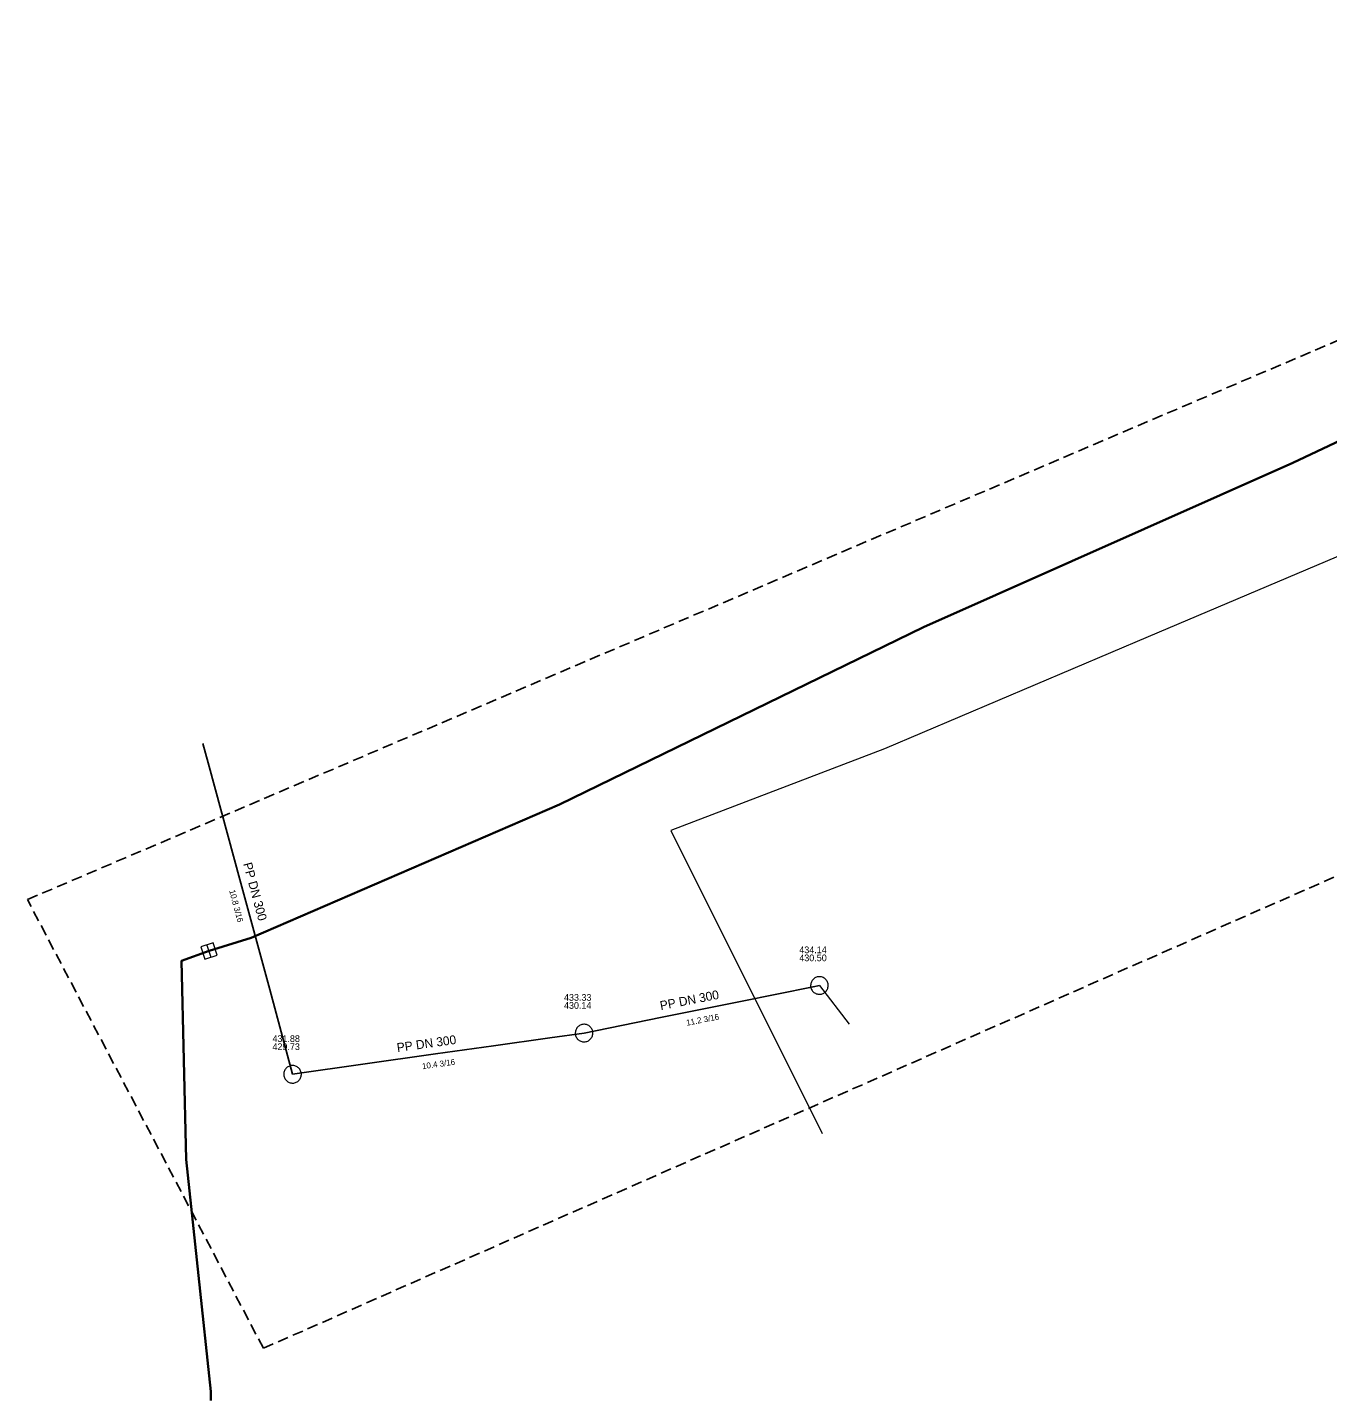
# Model space of a CAD drawing. Extents: x -772868 to -772180, y -1034353 to -1034014.
# Drawn here: x -772867.9 to -772693.4, y -1034353.3 to -1034169.1 of the extents above; entities that cross this region are included whole.
import ezdxf

# ---------------------------------------------------------------- set-up
doc = ezdxf.new("R2010")
doc.units = 0
doc.header["$LTSCALE"] = 0.48
doc.linetypes.add('MEDIUM_DASHED', pattern=[4.5, 3, -1.5])
doc.layers.add('14', color=7, linetype='Continuous')
doc.layers.add('3', color=7, linetype='Continuous')
for name, color, linetype, lineweight in [('15', 7, 'Continuous', 13), ('16', 7, 'Continuous', 35), ('2', 7, 'Continuous', 25), ('21', 7, 'Continuous', 13), ('4', 7, 'Continuous', 13), ('57', 7, 'Continuous', 13), ('59', 7, 'Continuous', 13), ('62', 7, 'MEDIUM_DASHED', 25)]:
    doc.layers.add(name, color=color, linetype=linetype, lineweight=lineweight)

msp = doc.modelspace()

# ---------------------------------------------------------------- linework, layer by layer
at = {"layer": '15'}
msp.add_line((-772843.222, -1034293.903), (-772843.811, -1034292.137), dxfattribs=at)
at = {"layer": '16'}
for points in [[(-772843.517, -1034293.021), (-772837.861, -1034291.239), (-772796.486, -1034273.344), (-772747.6, -1034249.561), (-772698.032, -1034227.521), (-772668.096, -1034213.403), (-772643.002, -1034202.219), (-772615.559, -1034189.903), (-772589.1, -1034178.815), (-772570.057, -1034172.495), (-772556.011, -1034186.133), (-772528.513, -1034217.168), (-772525.761, -1034220.679)], [(-772843.277, -1034353.339), (-772843.291, -1034352.14), (-772846.6, -1034321.004), (-772847.204, -1034294.32), (-772843.517, -1034293.021)]]:
    msp.add_lwpolyline(points, dxfattribs=at)
at = {"layer": '2'}
for points in [[(-772844.329, -1034265.199), (-772843.652, -1034267.766), (-772839.259, -1034283.904), (-772835.374, -1034298.172), (-772832.304, -1034309.565)], [(-772793.175, -1034304.035), (-772782.919, -1034301.948), (-772772.173, -1034299.782), (-772762.447, -1034297.822), (-772761.59, -1034297.65)], [(-772832.304, -1034309.565), (-772813.12, -1034306.832), (-772805.314, -1034305.729), (-772797.767, -1034304.662), (-772793.175, -1034304.035)]]:
    msp.add_lwpolyline(points, dxfattribs=at)
at = {"layer": '21'}
msp.add_lwpolyline([(-772844.611, -1034292.474), (-772844.064, -1034294.115), (-772842.423, -1034293.567), (-772842.97, -1034291.926)], close=True, dxfattribs=at)
at = {"layer": '4'}
for points in [[(-772760.409, -1034297.649), (-772760.415, -1034297.53), (-772760.433, -1034297.413), (-772760.462, -1034297.297), (-772760.503, -1034297.186), (-772760.555, -1034297.079), (-772760.618, -1034296.978), (-772760.691, -1034296.883), (-772760.772, -1034296.797), (-772760.862, -1034296.719), (-772760.96, -1034296.65), (-772761.063, -1034296.592), (-772761.172, -1034296.545), (-772761.286, -1034296.508), (-772761.402, -1034296.483), (-772761.52, -1034296.471), (-772761.639, -1034296.47), (-772761.758, -1034296.481), (-772761.874, -1034296.504), (-772761.988, -1034296.538), (-772762.098, -1034296.584), (-772762.203, -1034296.641), (-772762.301, -1034296.708), (-772762.392, -1034296.784), (-772762.475, -1034296.869), (-772762.549, -1034296.963), (-772762.613, -1034297.063), (-772762.667, -1034297.169), (-772762.71, -1034297.28), (-772762.742, -1034297.394), (-772762.761, -1034297.512), (-772762.769, -1034297.631), (-772762.765, -1034297.749), (-772762.749, -1034297.867), (-772762.721, -1034297.983), (-772762.682, -1034298.095), (-772762.631, -1034298.203), (-772762.57, -1034298.305), (-772762.499, -1034298.401), (-772762.419, -1034298.488), (-772762.33, -1034298.568), (-772762.234, -1034298.638), (-772762.131, -1034298.698), (-772762.023, -1034298.747), (-772761.91, -1034298.785), (-772761.794, -1034298.811), (-772761.676, -1034298.826), (-772761.557, -1034298.829), (-772761.439, -1034298.82), (-772761.321, -1034298.799), (-772761.207, -1034298.766), (-772761.097, -1034298.722), (-772760.991, -1034298.667), (-772760.892, -1034298.601), (-772760.799, -1034298.526), (-772760.715, -1034298.442), (-772760.64, -1034298.35), (-772760.574, -1034298.251), (-772760.518, -1034298.146), (-772760.474, -1034298.036), (-772760.44, -1034297.922), (-772760.419, -1034297.805), (-772760.409, -1034297.686)], [(-772791.995, -1034304.035), (-772792.001, -1034303.916), (-772792.019, -1034303.799), (-772792.048, -1034303.683), (-772792.089, -1034303.572), (-772792.141, -1034303.465), (-772792.204, -1034303.364), (-772792.277, -1034303.269), (-772792.358, -1034303.183), (-772792.448, -1034303.105), (-772792.546, -1034303.036), (-772792.649, -1034302.978), (-772792.758, -1034302.931), (-772792.872, -1034302.894), (-772792.988, -1034302.869), (-772793.106, -1034302.857), (-772793.225, -1034302.856), (-772793.344, -1034302.867), (-772793.46, -1034302.89), (-772793.574, -1034302.924), (-772793.684, -1034302.97), (-772793.789, -1034303.027), (-772793.887, -1034303.094), (-772793.978, -1034303.17), (-772794.061, -1034303.255), (-772794.135, -1034303.349), (-772794.199, -1034303.449), (-772794.253, -1034303.555), (-772794.296, -1034303.666), (-772794.328, -1034303.78), (-772794.347, -1034303.898), (-772794.355, -1034304.017), (-772794.351, -1034304.135), (-772794.335, -1034304.253), (-772794.307, -1034304.369), (-772794.268, -1034304.481), (-772794.217, -1034304.589), (-772794.156, -1034304.691), (-772794.085, -1034304.787), (-772794.005, -1034304.874), (-772793.916, -1034304.954), (-772793.82, -1034305.024), (-772793.717, -1034305.084), (-772793.609, -1034305.133), (-772793.496, -1034305.171), (-772793.38, -1034305.197), (-772793.262, -1034305.212), (-772793.143, -1034305.215), (-772793.025, -1034305.206), (-772792.907, -1034305.185), (-772792.793, -1034305.152), (-772792.683, -1034305.108), (-772792.577, -1034305.053), (-772792.478, -1034304.987), (-772792.385, -1034304.912), (-772792.301, -1034304.828), (-772792.226, -1034304.736), (-772792.16, -1034304.637), (-772792.104, -1034304.532), (-772792.06, -1034304.422), (-772792.026, -1034304.308), (-772792.005, -1034304.191), (-772791.995, -1034304.072)], [(-772831.124, -1034309.565), (-772831.13, -1034309.446), (-772831.148, -1034309.329), (-772831.177, -1034309.213), (-772831.218, -1034309.102), (-772831.27, -1034308.995), (-772831.333, -1034308.894), (-772831.406, -1034308.799), (-772831.487, -1034308.713), (-772831.577, -1034308.635), (-772831.675, -1034308.566), (-772831.778, -1034308.508), (-772831.887, -1034308.461), (-772832.001, -1034308.424), (-772832.117, -1034308.399), (-772832.235, -1034308.387), (-772832.354, -1034308.386), (-772832.473, -1034308.397), (-772832.589, -1034308.42), (-772832.703, -1034308.454), (-772832.813, -1034308.5), (-772832.918, -1034308.557), (-772833.016, -1034308.624), (-772833.107, -1034308.7), (-772833.19, -1034308.785), (-772833.264, -1034308.879), (-772833.328, -1034308.979), (-772833.382, -1034309.085), (-772833.425, -1034309.196), (-772833.457, -1034309.31), (-772833.476, -1034309.428), (-772833.484, -1034309.547), (-772833.48, -1034309.665), (-772833.464, -1034309.783), (-772833.436, -1034309.899), (-772833.397, -1034310.011), (-772833.346, -1034310.119), (-772833.285, -1034310.221), (-772833.214, -1034310.317), (-772833.134, -1034310.404), (-772833.045, -1034310.484), (-772832.949, -1034310.554), (-772832.846, -1034310.614), (-772832.738, -1034310.663), (-772832.625, -1034310.701), (-772832.509, -1034310.727), (-772832.391, -1034310.742), (-772832.272, -1034310.745), (-772832.154, -1034310.736), (-772832.036, -1034310.715), (-772831.922, -1034310.682), (-772831.812, -1034310.638), (-772831.706, -1034310.583), (-772831.607, -1034310.517), (-772831.514, -1034310.442), (-772831.43, -1034310.358), (-772831.355, -1034310.266), (-772831.289, -1034310.167), (-772831.233, -1034310.062), (-772831.189, -1034309.952), (-772831.155, -1034309.838), (-772831.134, -1034309.721), (-772831.124, -1034309.602)]]:
    msp.add_lwpolyline(points, close=True, dxfattribs=at)
at = {"layer": '57'}
msp.add_line((-772761.59, -1034297.65), (-772757.6, -1034302.85), dxfattribs=at)
at = {"layer": '59'}
msp.add_lwpolyline([(-772502.808, -1034176.621), (-772536.248, -1034191.403), (-772593.274, -1034216.812), (-772609.661, -1034218.584), (-772628.148, -1034217.801), (-772643.317, -1034219.07), (-772665.82, -1034228.054), (-772692.21, -1034240.173), (-772717.474, -1034250.871), (-772752.833, -1034265.915), (-772781.509, -1034276.864), (-772761.232, -1034317.521)], dxfattribs=at)
at = {"layer": '62'}
msp.add_lwpolyline([(-772867.887, -1034286.131), (-772867.882, -1034286.117), (-772230.643, -1034014.315), (-772215.439, -1034016.495), (-772184.418, -1034059.589), (-772836.208, -1034346.326)], close=True, dxfattribs=at)

# ---------------------------------------------------------------- texts
at = {"layer": '14'}
for s, p in [('434.14', (-772764.288, -1034293.317)), ('430.50', (-772764.288, -1034294.394)), ('433.33', (-772795.873, -1034299.702)), ('430.14', (-772795.873, -1034300.779)), ('431.88', (-772835.003, -1034305.232)), ('429.73', (-772835.003, -1034306.309))]:
    msp.add_text(s, height=0.9, dxfattribs=at).set_placement(p)
at = {"layer": '3'}
for s, height, rotation, p in [('PP DN 300 ', 1.2, 285, (-772838.948, -1034281.316)), ('10.8 3/16', 0.8, 285, (-772840.816, -1034284.93)), ('PP DN 300 ', 1.2, 11, (-772782.867, -1034300.959)), ('11.2 3/16', 0.8, 11, (-772779.383, -1034303.057)), ('PP DN 300 ', 1.2, 8, (-772818.223, -1034306.593)), ('10.4 3/16', 0.8, 8, (-772814.867, -1034308.893))]:
    msp.add_text(s, height=height, rotation=rotation, dxfattribs=at).set_placement(p)

doc.saveas('drawing.dxf')
